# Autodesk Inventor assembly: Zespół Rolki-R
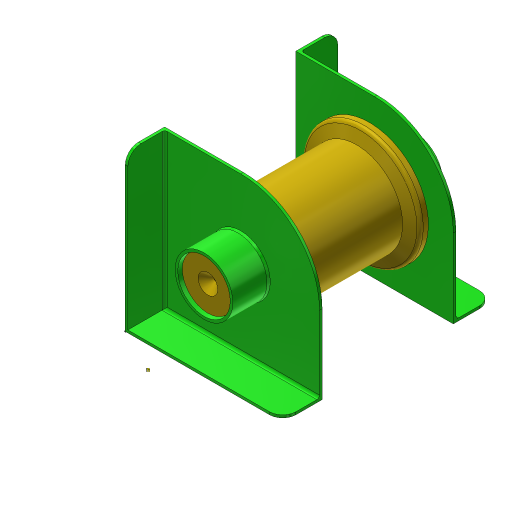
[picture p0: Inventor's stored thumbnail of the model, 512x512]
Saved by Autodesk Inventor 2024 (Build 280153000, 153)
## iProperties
Company: ATC
Created: 2023-03
Part Number: Zespół Rolki-R
Document SubType Name: Assembly
Designer: Andrzej Jaskulski
Checked By: A.J.
Engr Approved By: Andrzej Jaskulski
Mfg Approved By: Andrzej Jaskulski
Authority: A.J.
Title: A.J.: Kurs R2024-MEP
Author: Andrzej Jaskulski
Revision Number: 1/24
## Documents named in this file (4)
- C:\Users\AndJas\Documents\R2024-MEP\Obszar roboczy\SPEC\Zespół Rolki-R.iam
- C:\Users\AndJas\Documents\R2024-MEP\Obszar roboczy\SPEC\Podpora-RP.ipt
- C:\Users\AndJas\Documents\R2024-MEP\Obszar roboczy\SPEC\Podpora-RL.ipt
- C:\Users\AndJas\Documents\R2024-MEP\Obszar roboczy\SPEC\Rolka-R.ipt
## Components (3 placed, 3 different names)
1. Podpora-RP:1 — Równoległy:1, Równoległy:2, Zestawiający:1, Wstaw:1
2. Podpora-RL:1 — Równoległy:1, Równoległy:2, Zestawiający:1, Wstaw:2
3. Rolka-R:1 — Wstaw:1, Wstaw:2
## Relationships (5: Flush 2, Insert 2, Mate 1)
- Równoległy:1 [Flush]: Podpora-RP:1 ↔ Podpora-RL:1
- Równoległy:2 [Flush]: Podpora-RP:1 ↔ Podpora-RL:1
- Zestawiający:1 [Mate]: Podpora-RP:1 ↔ Podpora-RL:1
- Wstaw:1 [Insert]: Podpora-RP:1 ↔ Rolka-R:1
- Wstaw:2 [Insert]: Podpora-RL:1 ↔ Rolka-R:1
